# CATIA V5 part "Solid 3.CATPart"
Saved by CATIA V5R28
Part number: Part6.2
Bounding box of the stored display mesh (mm): x -75 to 75.038, y 0 to 600, z -20 to 20
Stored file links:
  H:\Maskiningenjör\Examensarbete\Klart\Klart & Skickas\Solid 3.CATPart
  H:\Examensarbete\Catia filer\Klar assembly\Klara blad av SOLID med hal\BladDesign.CATPart
  H:\Examensarbete\FullAssembly_KlartMedStativ\Assembly_Fullt+Stativ.CATProduct
  H:\Maskiningenjör\Examensarbete\Klart\Klart & Skickas\HJALPMEDEL.CATPart
  H:\Maskiningenjör\Examensarbete\Klart\Stativ o allt\AssemblyBlad_OriginalDesign.CATProduct
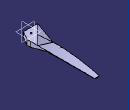
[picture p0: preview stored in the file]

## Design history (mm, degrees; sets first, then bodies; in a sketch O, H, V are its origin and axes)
Set1
  DatumPoint1 to DatumPoint3: linked copy from another document
Body1 (main body)
Body2 "Solid Blad"
  Solid1: solid without history
  Sketch1, origin (16.5222, 40.4632, 20), H (1, 0, 0), V (0, 1, 0), geometry linked from another document
  Hole1: placed by Sketch1, at (15.916, 40.4632, 20) direction (0, 0, -1), diameter 12, through (limit type 3)
  Sketch2 "Positioning sketch - Assembly Hole.4" on face of Solid1, origin (16.5222, 40.4632, 20), H (1, 0, 0), V (0, 1, 0)
    point P1 (-0.6062, 0)
    reference projected point E1 (-0.6062, 0) from vertex of DatumPoint3
    coincidence: E1 P1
